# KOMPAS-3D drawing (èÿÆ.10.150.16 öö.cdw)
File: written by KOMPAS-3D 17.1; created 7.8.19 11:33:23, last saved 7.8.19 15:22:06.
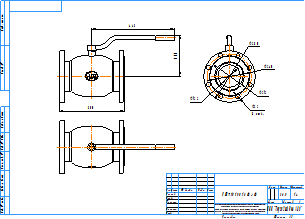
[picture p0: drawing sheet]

Sheet 1: A3, landscape

Title block, sheet 1: name: КШТ.10.150.16 Ф/Ф; material: Сталь 20  ГОСТ 1050-2013; mass: 36,5; sheets: 1; sheet format: A3; stored path: C:\Users\kka\KOMPAS_Work\Модели кранов для исследований\DN125\КШТ.10.125.16 СС.cdw

Views: Вид 1, Проекционный вид 2, Проекционный вид 3
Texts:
  kka
  adl
  Рама для чертежей
  Лит-Масса-Масштаб
  Материал-Предприятие
  Масштаб
  Изм.
  Лист
  № докум.
  Подп.
  Дата
  Лит.
  Разраб.
  Пров.
  Т.контр.
  Листов
  Внимание! Данный продукт является объектом авторского права ООО «Торговый Дом АДЛ».
  Запрещается изменение, копирование, распространение
  (в том числе путем копирования на другие сайты и ресурсы в Интернете)
  или любое иное использование информации и объектов без предварительного
  согласия правообладателя (ООО «Торговый Дом АДЛ»).
  Н.контр.
  Утв.
  ООО "Торговый дом АДЛ"
  Изменение
  Номер документа
  Подпись
  Обозначение документа
  Наименование изделия
  Масса изделия по ГОСТ 2.109-73
  Порядковый номер листа
  Общее количество листов в документе
  Характер работы, выполненной лицом, подписавшим документ
  Наименование или индекс предприятия, выпускающего документ
  Инв. № подл.
  Подп. и дата
  Взам. инв. №
  Инв. № дубл.
  Инвентарный номер подлинника по ГОСТ 2.501-68
  Подпись принявшего подлинник в отдел технической документации
  Инвентарный номер подлинника, взамен которого выпущен данный подлинник
  Инвентарный номер дубликата по ГОСТ 2.502-68
  Подпись принявшего дубликат в отдел технической документации
  Справ. №
  Перв. примен.
  Обозначение документа, взамен или на основании которого выпущен данный документ
  Обозначение документа, в котором впервые записан данный документ
  Подпись лица, копировавшего чертеж
  Обозначение формата листа
  !Рама для чертежа
Dimensions and other numbers on the sheet: 443; 220; 350; 122; 280; 240; 212; 22; 8 отв.; 1:4; 1; 36,5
